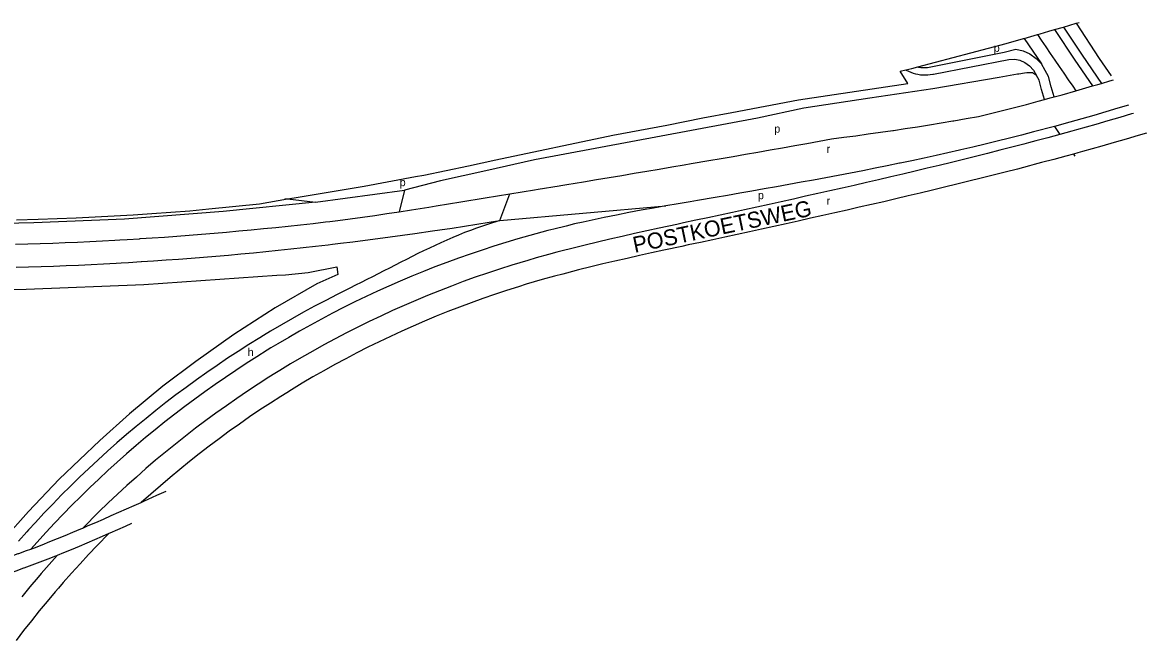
# Model space of a CAD drawing. Extents: x 155209 to 156755, y 386543 to 388502.
# Drawn here: x 156194 to 156755, y 388097 to 388406 of the extents above; entities that cross this region are included whole.
import ezdxf

# ---------------------------------------------------------------- set-up
doc = ezdxf.new("R2010")
doc.units = 0
for name, color, linetype in [('BLT_Basislijn', 7, 'Continuous'), ('BLT_Centroide', 7, 'Continuous'), ('BLT_Gemeentegrens', 7, 'Continuous'), ('BLT_Spoorlijn', 7, 'Continuous'), ('BLT_Straatnaam_hoofdweg', 7, 'Continuous'), ('BLT_Vlakafsluiter', 7, 'Continuous')]:
    doc.layers.add(name, color=color, linetype=linetype)

msp = doc.modelspace()

# ---------------------------------------------------------------- linework, layer by layer
at = {"layer": 'BLT_Basislijn'}
for p, q in [((156693.95, 388398.33), (156702.54, 388385.58)), ((156645.69, 388383.83), (156683.88, 388391.43)), ((156648.72, 388380.54), (156686.34, 388387.79)), ((156740.77, 388363.45), (156734.78, 388361.66)), ((156746.07, 388365.05), (156740.77, 388363.45)), ((156722.77, 388358.18), (156716.75, 388356.49)), ((156728.78, 388359.9), (156722.77, 388358.18)), ((156734.78, 388361.66), (156728.78, 388359.9)), ((156709.04, 388354.37), (156698.64, 388351.6)), ((156716.75, 388356.49), (156709.04, 388354.37)), ((156709.04, 388354.37), (156711.79, 388350.37)), ((156680.46, 388347), (156674.38, 388345.53)), ((156686.53, 388348.5), (156680.46, 388347)), ((156692.59, 388350.04), (156686.53, 388348.5)), ((156698.64, 388351.6), (156692.59, 388350.04)), ((156655.82, 388341.17), (156650.02, 388339.88)), ((156661.61, 388342.5), (156655.82, 388341.17)), ((156662.22, 388342.64), (156661.61, 388342.5)), ((156668.3, 388344.07), (156662.22, 388342.64)), ((156674.38, 388345.53), (156668.3, 388344.07)), ((156718.54, 388340.56), (156719.27, 388339.5)), ((156631.68, 388335.95), (156625.56, 388334.69)), ((156631.93, 388336), (156631.68, 388335.95)), ((156637.8, 388337.23), (156631.93, 388336)), ((156643.91, 388338.54), (156637.8, 388337.23)), ((156650.02, 388339.88), (156643.91, 388338.54)), ((156601.02, 388329.87), (156594.87, 388328.71)), ((156607.16, 388331.05), (156601.02, 388329.87)), ((156613.3, 388332.24), (156607.16, 388331.05)), ((156619.43, 388333.45), (156613.3, 388332.24)), ((156625.56, 388334.69), (156619.43, 388333.45)), ((156570.27, 388324.22), (156564.12, 388323.13)), ((156576.43, 388325.33), (156570.27, 388324.22)), ((156582.58, 388326.44), (156576.43, 388325.33)), ((156588.73, 388327.57), (156582.58, 388326.44)), ((156594.87, 388328.71), (156588.73, 388327.57)), ((156324.54, 388318.32), (156325.91, 388318.16)), ((156325.91, 388318.16), (156339.98, 388316.5)), ((156539.49, 388318.86), (156530.66, 388317.35)), ((156545.65, 388319.91), (156539.49, 388318.86)), ((156551.81, 388320.96), (156545.65, 388319.91)), ((156557.96, 388322.04), (156551.81, 388320.96)), ((156564.12, 388323.13), (156557.96, 388322.04)), ((156508.69, 388313.56), (156502.55, 388312.44)), ((156514.85, 388314.64), (156508.69, 388313.56)), ((156521, 388315.71), (156514.85, 388314.64)), ((156527.16, 388316.76), (156521, 388315.71)), ((156530.66, 388317.35), (156527.16, 388316.76)), ((156478.06, 388307.56), (156473.6, 388306.58)), ((156484.16, 388308.86), (156478.06, 388307.56)), ((156490.28, 388310.1), (156484.16, 388308.86)), ((156496.41, 388311.3), (156490.28, 388310.1)), ((156502.55, 388312.44), (156496.41, 388311.3))]:
    msp.add_line(p, q, dxfattribs=at)
for points in [[(156700.53, 388400.24), (156702.48, 388397.39), (156704.73, 388394.1), (156706.97, 388390.82), (156709.22, 388387.54), (156711.46, 388384.26), (156713.71, 388380.97), (156715.95, 388377.69), (156718.2, 388374.41), (156719.75, 388372.14)], [(156683.88, 388391.43), (156689.71, 388392.96), (156693.39, 388392.19), (156696.74, 388390.57), (156699.92, 388388.37), (156702.54, 388385.58)], [(156686.34, 388387.79), (156689.31, 388387.93), (156691.76, 388387.42), (156694.21, 388386.23), (156696.64, 388384.56), (156698.53, 388382.55), (156700.15, 388379.84)], [(156708.89, 388369.1), (156707.43, 388374.11), (156706.07, 388379.3), (156704.51, 388382.29), (156702.54, 388385.58)], [(156339.98, 388316.5), (156293.77, 388311.92), (156244.45, 388308.1), (156199.24, 388306.12), (156169.28, 388305.59), (156090.52, 388306.27), (156002.77, 388311.02), (155906.54, 388320.28), (155841.11, 388329.19), (155767.45, 388343.64), (155734.68, 388352.43), (155649.94, 388375.89), (155645.57, 388380.04)], [(156691.26, 388380.53), (156690.62, 388380.43), (156681.53, 388378.88), (156648.29, 388373.21), (156616.82, 388368.46), (156583.89, 388363.54), (156560.78, 388358.46), (156449.26, 388337.72), (156425.01, 388332.15), (156402.39, 388327.23), (156384.37, 388322.48)], [(156634.83, 388382.62), (156635.03, 388382.5), (156636.13, 388381.93), (156637.27, 388381.43), (156638.44, 388381.01), (156639.63, 388380.66), (156640.85, 388380.39), (156642.07, 388380.2), (156643.31, 388380.09), (156644.55, 388380.06), (156645.79, 388380.11), (156647.03, 388380.24), (156648.26, 388380.44), (156648.72, 388380.54)], [(156640.74, 388384.09), (156641.18, 388384), (156642.28, 388383.83), (156643.4, 388383.75), (156644.51, 388383.75), (156645.69, 388383.83)], [(156694.1, 388380.94), (156691.26, 388380.53)], [(156700.15, 388379.84), (156698.17, 388381.13), (156695.33, 388381.13), (156694.1, 388380.94)], [(156704.06, 388367.79), (156702.61, 388372.78), (156701.38, 388377.49), (156700.15, 388379.84)], [(156719.75, 388372.14), (156724.82, 388373.59), (156728.11, 388374.56)], [(156728.11, 388374.56), (156730.75, 388375.33), (156732.53, 388375.86)], [(156732.53, 388375.86), (156736.67, 388377.09), (156738.53, 388377.66)], [(156704.06, 388367.79), (156706.97, 388368.58), (156708.89, 388369.1)], [(156708.89, 388369.1), (156712.93, 388370.22), (156719.75, 388372.14)], [(156437, 388320.62), (156449.31, 388322.65), (156451.12, 388322.95), (156461.63, 388324.7), (156462.54, 388324.85), (156465.44, 388325.33), (156473.87, 388326.73), (156480.23, 388327.8), (156486.56, 388328.86), (156492.86, 388329.92), (156499.14, 388330.97), (156505.4, 388332.03), (156511.63, 388333.08), (156517.84, 388334.14), (156524.02, 388335.19), (156527.52, 388335.79), (156536.34, 388337.29), (156542.5, 388338.34), (156548.64, 388339.39), (156554.79, 388340.45), (156560.92, 388341.51), (156567.06, 388342.58), (156573.18, 388343.66), (156579.3, 388344.75), (156585.41, 388345.85), (156591.52, 388346.97), (156597.62, 388348.1), (156603.77, 388348.91), (156609.92, 388349.74), (156616.06, 388350.59), (156622.2, 388351.47), (156628.33, 388352.36), (156628.58, 388352.4), (156634.45, 388353.28), (156640.57, 388354.23), (156646.68, 388355.2), (156652.48, 388356.15), (156658.28, 388357.12), (156658.88, 388357.23), (156664.98, 388358.29), (156671.07, 388359.38), (156677.07, 388360.84), (156683.07, 388362.32), (156689.06, 388363.84), (156695.04, 388365.39), (156701.01, 388366.97), (156704.06, 388367.79)], [(156748.58, 388360.86), (156747.63, 388360.58), (156741.67, 388358.83), (156735.7, 388357.09), (156729.73, 388355.38), (156720.03, 388352.65), (156717.77, 388352.02), (156711.79, 388350.37)], [(156711.79, 388350.37), (156705.78, 388348.74), (156699.78, 388347.13), (156696.05, 388346.15), (156693.76, 388345.54), (156687.75, 388343.97), (156681.73, 388342.42), (156675.7, 388340.88), (156669.67, 388339.36), (156663.63, 388337.86), (156657.58, 388336.37), (156651.54, 388334.89), (156645.48, 388333.43), (156639.43, 388331.98), (156633.37, 388330.55), (156627.3, 388329.12), (156621.23, 388327.71), (156615.16, 388326.31), (156609.09, 388324.92), (156603.01, 388323.54), (156596.93, 388322.16), (156590.84, 388320.8), (156584.75, 388319.44), (156578.66, 388318.09), (156572.57, 388316.74), (156566.47, 388315.4), (156560.38, 388314.07), (156554.28, 388312.74), (156548.17, 388311.41), (156542.07, 388310.08), (156535.97, 388308.76), (156529.86, 388307.44), (156523.75, 388306.12), (156520.47, 388305.41), (156511.52, 388303.47), (156505.4, 388302.14), (156499.27, 388300.78), (156493.13, 388299.41), (156486.99, 388298), (156480.84, 388296.56), (156474.7, 388295.08), (156468.55, 388293.55), (156462.41, 388291.97), (156460.55, 388291.48), (156456.28, 388290.33), (156450.15, 388288.62), (156446.06, 388287.44), (156441.97, 388286.23), (156437.92, 388284.99), (156431.84, 388283.06), (156425.79, 388281.05), (156419.75, 388278.97), (156413.75, 388276.81), (156407.77, 388274.58), (156401.82, 388272.27), (156395.9, 388269.89), (156390.01, 388267.44), (156384.16, 388264.91), (156378.33, 388262.31), (156372.54, 388259.63), (156366.78, 388256.89), (156361.05, 388254.07), (156355.36, 388251.18), (156349.71, 388248.22), (156344.1, 388245.19), (156338.52, 388242.09), (156332.98, 388238.92), (156327.48, 388235.68), (156322.03, 388232.37), (156319.56, 388230.85), (156316.61, 388229), (156311.24, 388225.56), (156305.91, 388222.05), (156300.63, 388218.47), (156295.39, 388214.83), (156290.19, 388211.12), (156285.05, 388207.35), (156279.95, 388203.52), (156274.9, 388199.62), (156269.9, 388195.65), (156264.95, 388191.63), (156260.04, 388187.55), (156255.19, 388183.4), (156250.4, 388179.19), (156245.65, 388174.93), (156240.96, 388170.6), (156236.33, 388166.22), (156231.74, 388161.77), (156223.59, 388153.67)], [(156755.06, 388351.06), (156750.82, 388349.79), (156744.83, 388348.03), (156738.82, 388346.28), (156732.81, 388344.56), (156723.04, 388341.81), (156720.77, 388341.18), (156718.54, 388340.56)], [(156718.54, 388340.56), (156714.74, 388339.52), (156708.71, 388337.88), (156702.67, 388336.26), (156698.93, 388335.27), (156696.63, 388334.66), (156690.58, 388333.08), (156684.52, 388331.52), (156678.46, 388329.98), (156672.4, 388328.45), (156666.33, 388326.94), (156660.26, 388325.44), (156654.19, 388323.96), (156648.11, 388322.49), (156642.03, 388321.04), (156635.95, 388319.6), (156629.86, 388318.17), (156623.77, 388316.75), (156617.68, 388315.35), (156611.59, 388313.95), (156605.49, 388312.56), (156599.4, 388311.19), (156593.3, 388309.82), (156587.2, 388308.46), (156581.09, 388307.1), (156574.99, 388305.76), (156568.88, 388304.41), (156562.78, 388303.08), (156556.67, 388301.74), (156550.56, 388300.42), (156544.46, 388299.09), (156538.35, 388297.77), (156532.24, 388296.44), (156526.13, 388295.12), (156522.85, 388294.41), (156513.91, 388292.48), (156507.81, 388291.15), (156501.71, 388289.8), (156495.61, 388288.43), (156489.52, 388287.04), (156483.44, 388285.62), (156477.37, 388284.15), (156471.31, 388282.64), (156465.27, 388281.09), (156463.44, 388280.6), (156459.24, 388279.47), (156453.22, 388277.8), (156449.22, 388276.64), (156445.22, 388275.46), (156441.26, 388274.24), (156435.31, 388272.36), (156429.39, 388270.39), (156423.49, 388268.36), (156417.62, 388266.25), (156411.77, 388264.07), (156405.96, 388261.81), (156400.17, 388259.48), (156394.41, 388257.08), (156388.68, 388254.61), (156382.98, 388252.06), (156377.31, 388249.45), (156371.68, 388246.76), (156366.08, 388244.01), (156360.52, 388241.18), (156354.99, 388238.29), (156349.5, 388235.32), (156344.05, 388232.29), (156338.63, 388229.19), (156333.26, 388226.02), (156327.92, 388222.79), (156325.51, 388221.3), (156322.62, 388219.49), (156317.37, 388216.12), (156312.16, 388212.69), (156306.99, 388209.19), (156301.87, 388205.63), (156296.79, 388202.01), (156291.75, 388198.32), (156286.77, 388194.57), (156281.83, 388190.75), (156276.94, 388186.88), (156272.09, 388182.94), (156267.3, 388178.95), (156252.77, 388166.52)], [(156339.98, 388316.5), (156384.37, 388322.48)], [(156381.76, 388311.69), (156387.89, 388312.63), (156396.59, 388314.02), (156400.16, 388314.6), (156406.29, 388315.6), (156412.43, 388316.6), (156424.71, 388318.6), (156437, 388320.62)], [(156189.99, 388295.46), (156196.2, 388295.64), (156202.41, 388295.84), (156208.62, 388296.07), (156214.82, 388296.31), (156221.03, 388296.58), (156227.24, 388296.88), (156233.44, 388297.19), (156239.64, 388297.53), (156242.16, 388297.67), (156245.84, 388297.89), (156252.04, 388298.27), (156252.24, 388298.28), (156258.24, 388298.67), (156264.44, 388299.09), (156270.63, 388299.54), (156276.83, 388300.01), (156283.02, 388300.5), (156289.21, 388301.01), (156295.4, 388301.55), (156301.59, 388302.11), (156307.77, 388302.69), (156313.95, 388303.29), (156320.13, 388303.91), (156326.31, 388304.56), (156332.49, 388305.23), (156338.66, 388305.93), (156344.83, 388306.66), (156346.98, 388306.92), (156350.99, 388307.42), (156357.15, 388308.21), (156363.31, 388309.04), (156369.46, 388309.89), (156375.61, 388310.77), (156381.76, 388311.69)], [(156190.31, 388283.96), (156196.56, 388284.14), (156202.81, 388284.35), (156209.06, 388284.58), (156215.3, 388284.82), (156221.55, 388285.1), (156227.8, 388285.39), (156234.04, 388285.71), (156240.28, 388286.05), (156242.82, 388286.19), (156246.53, 388286.41), (156252.77, 388286.79), (156252.97, 388286.8), (156259.01, 388287.19), (156265.25, 388287.62), (156271.48, 388288.07), (156277.72, 388288.54), (156283.95, 388289.04), (156290.18, 388289.56), (156296.41, 388290.09), (156302.64, 388290.66), (156308.87, 388291.24), (156315.09, 388291.85), (156321.31, 388292.47), (156327.53, 388293.12), (156333.75, 388293.8), (156339.96, 388294.49), (156346.17, 388295.21), (156348.34, 388295.46), (156352.38, 388295.95), (156358.59, 388296.71), (156364.79, 388297.49), (156370.99, 388298.3), (156377.19, 388299.12), (156383.38, 388299.97), (156389.58, 388300.85), (156398.35, 388302.12), (156401.95, 388302.66), (156408.13, 388303.59), (156414.31, 388304.55), (156426.66, 388306.51), (156431.98, 388307.37)], [(156431.98, 388307.37), (156426.34, 388305.6), (156423.31, 388304.59), (156420.3, 388303.54), (156417.31, 388302.43), (156414.33, 388301.28), (156411.37, 388300.08), (156408.43, 388298.85), (156405.5, 388297.58), (156402.59, 388296.27), (156399.69, 388294.94), (156396.81, 388293.58), (156393.93, 388292.2), (156391.07, 388290.79), (156388.22, 388289.38), (156385.37, 388287.94), (156382.54, 388286.5), (156379.71, 388285.05), (156376.88, 388283.6), (156374.06, 388282.14), (156371.24, 388280.69), (156368.41, 388279.24), (156365.59, 388277.8), (156362.76, 388276.38), (156359.93, 388274.96), (156357.12, 388273.52)], [(156473.6, 388306.58), (156469.34, 388305.61), (156465.09, 388304.6), (156459.04, 388303.1), (156456, 388302.32), (156453, 388301.53), (156446.98, 388299.88), (156440.97, 388298.16), (156434.99, 388296.38)], [(156434.99, 388296.38), (156429.04, 388294.52), (156423.1, 388292.58), (156417.19, 388290.58), (156411.3, 388288.51), (156405.43, 388286.36), (156399.6, 388284.15), (156393.78, 388281.87), (156388, 388279.52), (156382.24, 388277.09), (156376.53, 388274.58), (156370.84, 388272), (156365.18, 388269.36), (156359.56, 388266.64), (156353.97, 388263.86), (156348.41, 388261.02), (156342.89, 388258.1), (156337.4, 388255.12), (156331.95, 388252.08), (156326.53, 388248.97), (156321.15, 388245.79), (156317.66, 388243.69), (156315.81, 388242.56), (156310.51, 388239.25), (156305.25, 388235.89), (156300.03, 388232.46), (156294.86, 388228.97), (156289.72, 388225.42), (156284.63, 388221.81), (156279.58, 388218.13), (156274.57, 388214.4), (156269.61, 388210.61), (156264.7, 388206.75), (156259.83, 388202.84), (156255.01, 388198.87), (156250.23, 388194.85), (156245.51, 388190.77), (156240.83, 388186.63), (156236.21, 388182.43), (156231.63, 388178.18), (156227.11, 388173.88), (156222.63, 388169.52), (156218.21, 388165.11), (156213.84, 388160.65), (156209.53, 388156.13), (156205.27, 388151.57), (156197.63, 388143.19)], [(156114.99, 388272.32), (156195.39, 388272.97), (156254.11, 388275.31), (156320.64, 388279.97), (156324.85, 388280.27), (156336.16, 388281.4), (156350.52, 388284.15), (156351.01, 388280.43), (156340.64, 388275.64), (156340.64, 388275.64), (156319.75, 388263.66), (156299.05, 388250.38), (156280.14, 388236.82), (156263.67, 388224.56), (156246.94, 388210.74), (156232.09, 388197.47), (156211.77, 388178.14), (156196.55, 388161.95), (156184.36, 388148.27)], [(156357.12, 388273.52), (156356.37, 388273.16), (156350.7, 388270.34), (156345.07, 388267.45), (156339.47, 388264.49), (156333.9, 388261.47), (156328.37, 388258.39), (156322.88, 388255.23), (156317.43, 388252.01), (156313.89, 388249.88), (156312.02, 388248.73), (156306.64, 388245.38), (156301.31, 388241.97), (156296.02, 388238.5), (156290.77, 388234.96), (156285.56, 388231.36), (156280.4, 388227.69), (156275.28, 388223.97), (156270.2, 388220.18), (156265.17, 388216.34), (156260.19, 388212.43), (156255.25, 388208.47), (156250.37, 388204.44), (156245.53, 388200.36), (156240.73, 388196.22), (156235.99, 388192.03), (156231.3, 388187.77), (156226.66, 388183.47), (156222.08, 388179.1), (156217.54, 388174.68), (156213.06, 388170.21), (156208.63, 388165.69), (156204.26, 388161.11), (156199.94, 388156.48), (156196.51, 388152.72), (156195.68, 388151.8), (156191.47, 388147.07)], [(156252.77, 388166.52), (156254.14, 388167.14), (156260.69, 388170.07), (156265.28, 388172.1)], [(156223.59, 388153.67), (156226.41, 388154.88), (156230.24, 388156.53), (156234.05, 388158.2), (156237.86, 388159.88), (156241.67, 388161.56), (156245.48, 388163.26), (156249.28, 388164.96), (156252.77, 388166.52)], [(156247.98, 388155.89), (156244.82, 388154.48), (156241, 388152.79), (156237.17, 388151.1), (156236.73, 388150.91)], [(156236.73, 388150.91), (156230.83, 388144.89), (156226.52, 388140.39), (156222.26, 388135.82), (156218.06, 388131.21), (156213.92, 388126.54), (156211.43, 388123.69), (156209.83, 388121.82), (156205.81, 388117.05), (156201.84, 388112.24), (156197.94, 388107.37), (156194.1, 388102.45), (156190.32, 388097.49)], [(156197.63, 388143.19), (156199.44, 388143.87), (156203.32, 388145.37), (156207.2, 388146.89), (156211.06, 388148.44), (156214.91, 388150.02), (156218.75, 388151.62), (156222.59, 388153.24), (156223.59, 388153.67)], [(156236.73, 388150.91), (156233.33, 388149.42), (156229.48, 388147.76), (156225.62, 388146.11), (156221.75, 388144.47), (156217.87, 388142.86), (156213.97, 388141.26), (156210.82, 388140)], [(156183.81, 388138.24), (156187.58, 388139.54), (156191.43, 388140.9), (156191.64, 388140.98), (156195.55, 388142.41), (156197.63, 388143.19)], [(156210.82, 388140), (156210.06, 388139.69), (156206.14, 388138.15), (156202.2, 388136.63), (156198.24, 388135.14), (156194.27, 388133.69), (156194.05, 388133.61), (156190.14, 388132.22), (156187.58, 388131.34)], [(156210.82, 388140), (156205.46, 388133.96), (156202.92, 388131.04), (156201.28, 388129.13), (156197.17, 388124.26), (156193.11, 388119.33)]]:
    msp.add_lwpolyline(points, dxfattribs=at)
at = {"layer": 'BLT_Gemeentegrens'}
for p, q in [((156709.09, 388402.72), (156713.56, 388404.02)), ((156713.56, 388404.02), (156719.99, 388405.88)), ((156719.99, 388405.88), (156721.43, 388406.3)), ((156693.95, 388398.33), (156700.53, 388400.24))]:
    msp.add_line(p, q, dxfattribs=at)
for points in [[(156700.53, 388400.24), (156702.01, 388400.67), (156706.28, 388401.91), (156709.09, 388402.72)], [(156640.74, 388384.09), (156685.01, 388395.74), (156693.53, 388398.21), (156693.95, 388398.33)], [(156325.91, 388318.16), (156329.2, 388318.75), (156364.18, 388324.45), (156389.85, 388329.39), (156393.95, 388330.05), (156416.41, 388334.62), (156429.96, 388337.65), (156488.42, 388350), (156515.42, 388355.07), (156533.48, 388358.58), (156547.95, 388361.32), (156581.14, 388367.65), (156635.84, 388375.79), (156631.92, 388381.93), (156634.83, 388382.62)], [(156634.83, 388382.62), (156637.81, 388383.32), (156640.74, 388384.09)], [(156190.55, 388307.75), (156201.36, 388308.08), (156210.84, 388308.36), (156220.32, 388308.7), (156229.79, 388309.12), (156239.27, 388309.61), (156248.74, 388310.17), (156258.2, 388310.79), (156267.66, 388311.49), (156277.11, 388312.26), (156286.56, 388313.1), (156311.87, 388315.62), (156325.91, 388318.16)]]:
    msp.add_lwpolyline(points, dxfattribs=at)
at = {"layer": 'BLT_Spoorlijn'}
for p, q in [((156709.09, 388402.72), (156719.28, 388387.39)), ((156713.56, 388404.02), (156722.92, 388389.94)), ((156719.99, 388405.88), (156731.46, 388388.22))]:
    msp.add_line(p, q, dxfattribs=at)
for points in [[(156719.28, 388387.39), (156728.11, 388374.56)], [(156722.92, 388389.94), (156732.53, 388375.86)], [(156731.46, 388388.22), (156737.39, 388379.56)]]:
    msp.add_lwpolyline(points, dxfattribs=at)
at = {"layer": 'BLT_Vlakafsluiter'}
for p, q in [((156384.37, 388322.48), (156381.76, 388311.69)), ((156431.98, 388307.37), (156437, 388320.62)), ((156431.98, 388307.37), (156514.85, 388314.64))]:
    msp.add_line(p, q, dxfattribs=at)

# ---------------------------------------------------------------- texts
at = {"layer": 'BLT_Centroide'}
for s, p in [('p', (156678.75, 388391.63)), ('p', (156569.11, 388351.22)), ('r', (156595.24, 388341.13)), ('p', (156381.97, 388324.51)), ('p', (156560.95, 388317.99)), ('r', (156595.24, 388315.19)), ('h', (156306.03, 388239.61))]:
    msp.add_text(s, height=4, dxfattribs=at).set_placement(p)
at = {"layer": 'BLT_Straatnaam_hoofdweg'}
msp.add_text('POSTKOETSWEG', height=8, rotation=11.8674, dxfattribs=at).set_placement((156499.36, 388291.14))

doc.saveas('drawing.dxf')
